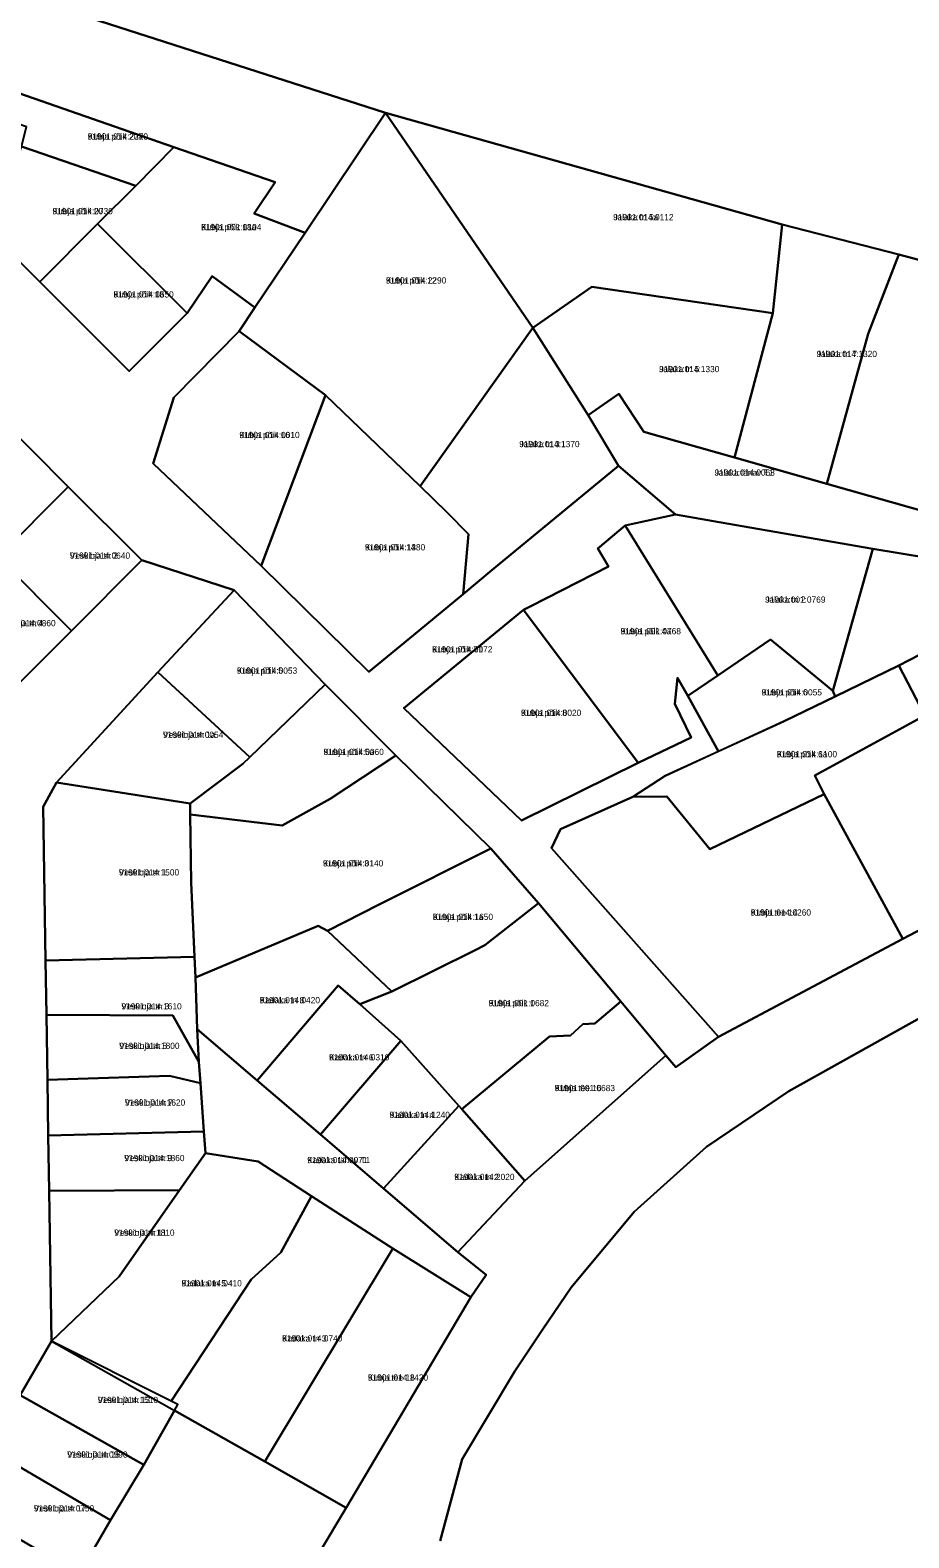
# Model space of a CAD drawing. Extents: x 675810 to 681273, y 6411190 to 6417565.
# Drawn here: x 678392.3 to 678603.7, y 6413180.1 to 6413542.7 of the extents above; entities that cross this region are included whole.
import ezdxf

# ---------------------------------------------------------------- set-up
doc = ezdxf.new("R2010")
doc.units = 0
for name, color, linetype in [('L_AADRESS', 7, 'Continuous'), ('PIIR', 7, 'Continuous'), ('TUNNUS', 7, 'Continuous')]:
    doc.layers.add(name, color=color, linetype=linetype)

msp = doc.modelspace()

# ---------------------------------------------------------------- linework, layer by layer
at = {"layer": 'PIIR'}
for points in [[(678295.76, 6413554.98), (678293.96, 6413581.95), (678477.82, 6413522.85), (678458.5, 6413494.01), (678446.21, 6413498.66), (678451.25, 6413506.22), (678426.9, 6413514.62), (678389.61, 6413527.56), (678354.34, 6413542.49), (678352.55, 6413514.04), (678351.25, 6413513.9), (678354.14, 6413492.79), (678351.28, 6413483.5), (678325.9, 6413492.81), (678311.61, 6413482.73), (678306.63, 6413471.48), (678306.92, 6413457.06), (678308.78, 6413450.62), (678302.83, 6413437.81), (678298.35, 6413440.16), (678297.78, 6413528.19)], [(678426.9, 6413514.62), (678417.74, 6413505.28), (678390.19, 6413514.73), (678391.4, 6413519.53), (678387.5, 6413520.85), (678389.61, 6413527.56)], [(678513.24, 6413471.19), (678486.13, 6413433.07), (678463.36, 6413454.98), (678442.64, 6413470.33), (678446.41, 6413476.03), (678458.5, 6413494.01), (678477.82, 6413522.85)], [(678477.82, 6413522.85), (678573.26, 6413496.02), (678571.03, 6413474.68), (678527.43, 6413480.98), (678513.24, 6413471.19)], [(678386.16, 6413490.69), (678382.36, 6413492.05), (678390.19, 6413514.73), (678417.74, 6413505.28), (678408.5, 6413496.18), (678394.65, 6413482.21)], [(678417.74, 6413505.28), (678426.9, 6413514.62), (678451.25, 6413506.22), (678446.21, 6413498.66), (678458.5, 6413494.01), (678446.41, 6413476.03), (678436.09, 6413483.57), (678430.1, 6413474.66), (678408.5, 6413496.18)], [(678394.65, 6413482.21), (678408.5, 6413496.18), (678430.1, 6413474.66), (678416.16, 6413460.72)], [(678571.03, 6413474.68), (678573.26, 6413496.02), (678601.35, 6413488.77), (678593.96, 6413469.73), (678584.01, 6413433.67), (678561.79, 6413440)], [(678593.96, 6413469.73), (678601.35, 6413488.77), (678622.33, 6413483.15), (678627.53, 6413450.29), (678630.17, 6413428.46), (678609.77, 6413426.33), (678584.01, 6413433.67)], [(678513.24, 6413471.19), (678527.43, 6413480.98), (678571.03, 6413474.68), (678561.79, 6413440), (678540, 6413446.17), (678533.98, 6413455.3), (678526.6, 6413450.17)], [(678421.94, 6413438.53), (678426.87, 6413454.38), (678442.64, 6413470.33), (678463.36, 6413454.98), (678447.92, 6413413.95)], [(678497.82, 6413421.55), (678492.57, 6413426.8), (678486.13, 6413433.07), (678513.24, 6413471.19), (678526.6, 6413450.17), (678533.88, 6413437.98), (678503.42, 6413412.83), (678496.47, 6413407.1)], [(678447.92, 6413413.95), (678463.36, 6413454.98), (678486.13, 6413433.07), (678492.57, 6413426.8), (678497.82, 6413421.55), (678496.47, 6413407.1), (678485.89, 6413398.35), (678473.84, 6413388.45)], [(678526.6, 6413450.17), (678533.98, 6413455.3), (678540, 6413446.17), (678561.79, 6413440), (678584.01, 6413433.67), (678609.77, 6413426.33), (678630.17, 6413428.46), (678631.49, 6413420.57), (678608.2, 6413415.87), (678595.07, 6413418.02), (678559.91, 6413424.12), (678547.61, 6413426.26), (678533.88, 6413437.98)], [(678384.53, 6413415.96), (678354.7, 6413416.01), (678348.57, 6413416.03), (678317.48, 6413417.46), (678306.94, 6413412.98), (678309.26, 6413408.27), (678292.44, 6413401.19), (678293.98, 6413418.76), (678317.17, 6413427.45), (678331, 6413421.85), (678345.66, 6413423.1), (678356.55, 6413422.98), (678383.8, 6413450.61), (678401.49, 6413432.94)], [(678402.22, 6413398.29), (678384.53, 6413415.96), (678401.49, 6413432.94), (678419.18, 6413415.28)], [(678557.76, 6413387.54), (678535.45, 6413423.61), (678547.61, 6413426.26), (678559.91, 6413424.12), (678595.07, 6413418.02), (678585.46, 6413383.81), (678570.48, 6413396.2)], [(678535.45, 6413423.61), (678557.76, 6413387.54), (678550.59, 6413382.64), (678548.06, 6413386.98), (678547.45, 6413380.71), (678551.39, 6413372.61), (678538.62, 6413366.54), (678511.05, 6413403.34), (678512.66, 6413404.15), (678520.31, 6413408.07), (678531.49, 6413413.74), (678528.93, 6413418.05)], [(678585.46, 6413383.81), (678595.07, 6413418.02), (678608.2, 6413415.87), (678631.49, 6413420.57), (678633.57, 6413405.93), (678618.75, 6413398.88), (678601.3, 6413389.95), (678586.02, 6413382.5)], [(678348.37, 6413407.11), (678319.56, 6413412.48), (678309.26, 6413408.27), (678306.94, 6413412.98), (678317.48, 6413417.46), (678348.57, 6413416.03), (678354.7, 6413416.01), (678384.53, 6413415.96), (678402.22, 6413398.29), (678385.26, 6413381.3), (678358.97, 6413406.95)], [(678441.41, 6413408.05), (678463.27, 6413385.35), (678445.14, 6413367.88), (678422.99, 6413388.32)], [(678627.38, 6413341.21), (678613.08, 6413367.48), (678608.23, 6413376.32), (678607.62, 6413377.91), (678601.3, 6413389.95), (678618.75, 6413398.88), (678633.57, 6413405.93), (678637.71, 6413407.92), (678650.35, 6413387.95), (678630.94, 6413377.1), (678645.38, 6413350.73)], [(678538.62, 6413366.54), (678510.55, 6413352.67), (678482.22, 6413379.65), (678511.05, 6413403.34)], [(678557.76, 6413387.54), (678570.48, 6413396.2), (678585.46, 6413383.81), (678586.02, 6413382.5), (678573.76, 6413376.53), (678557.92, 6413369.29), (678550.59, 6413382.64)], [(678545.52, 6413358.41), (678537.34, 6413358.32), (678545.11, 6413363.44), (678557.92, 6413369.3), (678573.76, 6413376.53), (678586.02, 6413382.5), (678601.3, 6413389.95), (678607.62, 6413377.91), (678581.15, 6413363.52), (678583.38, 6413358.97), (678555.83, 6413345.79)], [(678422.99, 6413388.32), (678445.14, 6413367.88), (678443.51, 6413366.32), (678430.85, 6413356.78), (678398.62, 6413361.82)], [(678463.27, 6413385.35), (678480.26, 6413368.28), (678464.49, 6413357.91), (678452.98, 6413351.45), (678430.78, 6413354.14), (678430.85, 6413356.78), (678443.51, 6413366.32), (678445.14, 6413367.88)], [(678583.38, 6413358.97), (678581.15, 6413363.52), (678607.62, 6413377.91), (678608.23, 6413376.32), (678613.08, 6413367.48), (678627.38, 6413341.21), (678628.99, 6413338.24), (678602.33, 6413324.19)], [(678432.09, 6413314.94), (678431.86, 6413319.86), (678431.02, 6413337.78), (678430.78, 6413354.14), (678452.98, 6413351.45), (678464.49, 6413357.91), (678480.26, 6413368.28), (678503.19, 6413345.91), (678476.32, 6413332.49), (678463.84, 6413326.15), (678461.61, 6413327.29)], [(678431.86, 6413319.86), (678396.01, 6413318.99), (678395.44, 6413355.92), (678398.62, 6413361.82), (678430.85, 6413356.78), (678430.78, 6413354.14), (678431.02, 6413337.78)], [(678602.33, 6413324.19), (678557.93, 6413300.6), (678517.78, 6413346), (678519.93, 6413350.6), (678537.34, 6413358.32), (678545.52, 6413358.41), (678555.83, 6413345.79), (678583.38, 6413358.97)], [(678463.84, 6413326.15), (678476.32, 6413332.49), (678503.19, 6413345.91), (678514.61, 6413332.78), (678512.39, 6413331.01), (678501.73, 6413322.67), (678499.37, 6413321.5), (678479.34, 6413311.54)], [(678512.39, 6413331.01), (678514.61, 6413332.78), (678534.4, 6413309.14), (678528.18, 6413303.83), (678525.32, 6413303.69), (678522.35, 6413300.94), (678517.28, 6413300.68), (678496.18, 6413283.21), (678495.48, 6413284), (678481.52, 6413299.63), (678471.66, 6413308.5), (678479.34, 6413311.54), (678499.37, 6413321.5), (678501.73, 6413322.67)], [(678466.42, 6413312.94), (678446.94, 6413290.13), (678432.5, 6413302.46), (678432.09, 6413314.94), (678461.61, 6413327.29), (678463.84, 6413326.15), (678479.34, 6413311.54), (678471.66, 6413308.5)], [(678426.61, 6413305.8), (678396.21, 6413305.95), (678396.01, 6413318.99), (678431.86, 6413319.86), (678432.09, 6413314.94), (678432.5, 6413302.46), (678432.92, 6413294.58)], [(678446.94, 6413290.13), (678466.42, 6413312.94), (678471.66, 6413308.5), (678481.52, 6413299.63), (678462.15, 6413277.13)], [(678528.18, 6413303.83), (678534.4, 6413309.14), (678545.3, 6413296.17), (678511.35, 6413266), (678496.18, 6413283.21), (678517.28, 6413300.68), (678522.35, 6413300.94), (678525.32, 6413303.69)], [(678425.81, 6413291.23), (678396.46, 6413290.3), (678396.21, 6413305.95), (678426.61, 6413305.8), (678432.92, 6413294.58), (678433.29, 6413289.47)], [(678432.5, 6413302.46), (678446.94, 6413290.13), (678462.15, 6413277.13), (678477.36, 6413264.14), (678495.22, 6413248.88), (678502.03, 6413243.37), (678498.35, 6413238.03), (678479.59, 6413249.75), (678460.03, 6413262.33), (678447.16, 6413270.61), (678434.5, 6413272.68), (678434.13, 6413277.9), (678433.29, 6413289.47), (678432.92, 6413294.58)], [(678462.15, 6413277.13), (678481.52, 6413299.63), (678495.48, 6413284), (678477.36, 6413264.14)], [(678434.13, 6413277.9), (678396.67, 6413276.93), (678396.46, 6413290.3), (678425.81, 6413291.23), (678433.29, 6413289.47)], [(678495.22, 6413248.88), (678477.36, 6413264.14), (678495.48, 6413284), (678496.18, 6413283.21), (678511.35, 6413266)], [(678428.22, 6413263.74), (678396.88, 6413263.56), (678396.67, 6413276.93), (678434.13, 6413277.9), (678434.5, 6413272.68)], [(678452.59, 6413248.73), (678445.5, 6413242.24), (678426.27, 6413212.98), (678397.45, 6413227.43), (678413.7, 6413243.03), (678428.22, 6413263.74), (678434.5, 6413272.68), (678447.16, 6413270.61), (678460.03, 6413262.33)], [(678413.7, 6413243.03), (678397.45, 6413227.43), (678396.88, 6413263.56), (678428.22, 6413263.74)], [(678427.06, 6413210.73), (678427.88, 6413212.17), (678426.27, 6413212.98), (678445.5, 6413242.24), (678452.59, 6413248.73), (678460.03, 6413262.33), (678479.59, 6413249.75), (678448.79, 6413198.47)], [(678479.59, 6413249.75), (678498.35, 6413238.03), (678468.34, 6413187.35), (678448.79, 6413198.47)], [(678397.45, 6413227.43), (678427.06, 6413210.73), (678419.68, 6413197.67), (678389.92, 6413214.47)], [(678389.92, 6413214.47), (678419.68, 6413197.67), (678411.67, 6413184.37), (678382.31, 6413201.53)], [(678435.46, 6413132.45), (678399.43, 6413154.72), (678395.78, 6413156.89), (678366.24, 6413174.06), (678374.74, 6413188.57), (678404.1, 6413171.42), (678411.67, 6413184.37), (678419.68, 6413197.67), (678427.06, 6413210.73), (678448.79, 6413198.47), (678468.34, 6413187.35)], [(678382.31, 6413201.53), (678411.67, 6413184.37), (678404.1, 6413171.42), (678374.74, 6413188.57)]]:
    msp.add_lwpolyline(points, close=True, dxfattribs=at)
for points in [[(678858.38, 6413443.59), (678779.84, 6413441.57), (678734.44, 6413455.67), (678700.16, 6413460.78), (678680.14, 6413465.61), (678622.33, 6413483.15), (678601.35, 6413488.77), (678573.26, 6413496.02), (678477.82, 6413522.85), (678293.96, 6413581.95)], [(678386.16, 6413490.69), (678394.65, 6413482.21), (678416.16, 6413460.72), (678430.1, 6413474.66), (678436.09, 6413483.57), (678446.41, 6413476.03), (678442.64, 6413470.33), (678426.87, 6413454.38), (678421.94, 6413438.53), (678447.92, 6413413.95), (678473.84, 6413388.45), (678485.89, 6413398.35), (678496.47, 6413407.1), (678503.42, 6413412.83), (678533.88, 6413437.98), (678547.61, 6413426.26), (678535.45, 6413423.61), (678528.93, 6413418.05), (678531.49, 6413413.74), (678520.31, 6413408.07), (678512.66, 6413404.15), (678511.05, 6413403.34), (678482.22, 6413379.65), (678510.55, 6413352.67), (678538.62, 6413366.54), (678551.39, 6413372.61), (678547.45, 6413380.71), (678548.06, 6413386.98), (678550.59, 6413382.64), (678557.92, 6413369.29), (678545.11, 6413363.44), (678537.34, 6413358.32), (678519.93, 6413350.6), (678517.78, 6413346), (678557.93, 6413300.6), (678547.71, 6413293.36), (678545.3, 6413296.17), (678534.4, 6413309.14), (678514.61, 6413332.78), (678503.19, 6413345.91), (678480.26, 6413368.28), (678463.27, 6413385.35), (678441.41, 6413408.05), (678419.18, 6413415.28), (678401.49, 6413432.94), (678383.8, 6413450.61)], [(678435.46, 6413132.45), (678468.34, 6413187.35), (678498.35, 6413238.03), (678502.03, 6413243.37), (678495.22, 6413248.88), (678511.35, 6413266), (678545.3, 6413296.17), (678547.71, 6413293.36), (678557.93, 6413300.6), (678602.33, 6413324.19), (678628.99, 6413338.24), (678627.38, 6413341.21), (678645.38, 6413350.73), (678665.04, 6413361.36), (678666.81, 6413358.15), (678710.5, 6413387.05), (678745.28, 6413416.24), (678779.84, 6413441.57), (678858.38, 6413443.59)], [(678385.26, 6413381.3), (678402.22, 6413398.29), (678419.18, 6413415.28), (678441.41, 6413408.05), (678422.99, 6413388.32), (678398.62, 6413361.82), (678395.44, 6413355.92), (678396.01, 6413318.99), (678396.21, 6413305.95), (678396.46, 6413290.3), (678396.67, 6413276.93), (678396.88, 6413263.56), (678397.45, 6413227.43), (678389.92, 6413214.47)], [(678837.49, 6413412.16), (678813.86, 6413408.99), (678791.56, 6413403.6), (678770.01, 6413395.44), (678749.7, 6413384.68), (678709.22, 6413356.39), (678663.86, 6413332.17), (678641.85, 6413320.32), (678618.17, 6413311.55), (678607.18, 6413305.63), (678574.88, 6413287.6), (678555.09, 6413274.2), (678537.66, 6413258.57), (678522.47, 6413240.32), (678515.7, 6413230.29), (678508.92, 6413220.26), (678502.59, 6413209.66), (678496.26, 6413199.06), (678490.99, 6413179.42)], [(678490.99, 6413179.42), (678496.26, 6413199.06), (678502.59, 6413209.66), (678508.92, 6413220.26), (678515.7, 6413230.29), (678522.47, 6413240.32), (678537.66, 6413258.57), (678555.09, 6413274.2), (678574.88, 6413287.6), (678607.18, 6413305.63), (678618.17, 6413311.55), (678641.85, 6413320.32), (678663.86, 6413332.17), (678709.22, 6413356.39), (678749.7, 6413384.68), (678770.01, 6413395.44), (678791.56, 6413403.6), (678802.33, 6413329.46), (678796.69, 6413254.97), (678802.47, 6413186.73), (678806.01, 6413088.59)]]:
    msp.add_lwpolyline(points, dxfattribs=at)

# ---------------------------------------------------------------- texts
at = {"layer": 'L_AADRESS'}
for s, p in [('Kubja põik 20a', (678406.16, 6413516.42)), ('Kubja põik 20', (678397.7, 6413498.47)), ('Jalaka tn 5a', (678532.62, 6413497.02)), ('Kubja põik 18a', (678433.44, 6413494.64)), ('Kubja põik 12', (678477.94, 6413481.81)), ('Kubja põik 18', (678412.35, 6413478.45)), ('Jalaka tn 7', (678581.57, 6413464.12)), ('Jalaka tn 5', (678543.65, 6413460.49)), ('Kubja põik 16', (678442.65, 6413444.63)), ('Jalaka tn 3', (678510.01, 6413442.45)), ('Jalaka tänav T1', (678556.99, 6413435.59)), ('Kubja põik 14', (678472.87, 6413417.62)), ('Veskioja tn 2', (678401.86, 6413415.62)), ('Jalaka tn 2', (678569.18, 6413405.04)), ('Veskioja tn 4', (678383.93, 6413399.38)), ('Kubja põik 4a', (678534.4, 6413397.44)), ('Kubja põik T1', (678489.03, 6413393.08)), ('Kubja põik 5', (678442.06, 6413387.96)), ('Kubja põik 6', (678568.33, 6413382.74)), ('Kubja põik 8', (678510.42, 6413377.81)), ('Veskioja tn 1a', (678424.28, 6413372.55)), ('Kubja põik 5a', (678462.91, 6413368.4)), ('Kubja põik 6a', (678571.97, 6413367.87)), ('Kubja põik 3', (678462.77, 6413341.61)), ('Veskioja tn 1', (678413.65, 6413339.44)), ('Kubja tee 14', (678565.7, 6413329.79)), ('Kubja põik 1a', (678489.19, 6413328.73)), ('Kadaka tn 8', (678447.55, 6413308.71)), ('Kubja põik 1', (678502.64, 6413308)), ('Veskioja tn 3', (678414.27, 6413307.22)), ('Veskioja tn 5', (678413.75, 6413297.71)), ('Kadaka tn 6', (678464.23, 6413294.96)), ('Kubja tee 16', (678518.53, 6413287.57)), ('Veskioja tn 7', (678415.12, 6413284.08)), ('Kadaka tn 4', (678478.81, 6413281.11)), ('Veskioja tn 9', (678414.95, 6413270.73)), ('Kadaka tänav T1', (678458.97, 6413270.25)), ('Kadaka tn 2', (678494.36, 6413266.19)), ('Veskioja tn 11', (678412.55, 6413252.79)), ('Kadaka tn 5', (678428.74, 6413240.61)), ('Kadaka tn 3', (678452.93, 6413227.36)), ('Kubja tee 18', (678473.57, 6413217.95)), ('Veskioja tn 13', (678408.58, 6413212.55)), ('Veskioja tn 15', (678401.25, 6413199.42)), ('Veskioja tn 17', (678393.2, 6413186.48))]:
    msp.add_text(s, height=1.5, dxfattribs=at).set_placement(p)
at = {"layer": 'TUNNUS'}
for s, p in [('91901:014:2270', (678406.16, 6413516.42)), ('91901:014:0730', (678397.7, 6413498.47)), ('91901:014:0112', (678532.62, 6413497.02)), ('91901:001:0104', (678433.44, 6413494.64)), ('91901:014:2290', (678477.94, 6413481.81)), ('91901:014:0650', (678412.35, 6413478.45)), ('91901:014:1320', (678581.57, 6413464.12)), ('91901:014:1330', (678543.65, 6413460.49)), ('91901:014:0010', (678442.65, 6413444.63)), ('91901:014:1370', (678510.01, 6413442.45)), ('91901:014:0068', (678556.99, 6413435.59)), ('91901:014:1380', (678472.87, 6413417.62)), ('91901:014:0640', (678401.86, 6413415.62)), ('91901:001:0769', (678569.18, 6413405.04)), ('91901:014:0860', (678383.93, 6413399.38)), ('91901:001:0768', (678534.4, 6413397.44)), ('91901:014:0072', (678489.03, 6413393.08)), ('91901:014:0053', (678442.06, 6413387.96)), ('91901:014:0055', (678568.33, 6413382.74)), ('91901:014:0020', (678510.42, 6413377.81)), ('91901:014:0054', (678424.28, 6413372.55)), ('91901:014:0060', (678462.91, 6413368.4)), ('91901:014:1100', (678571.97, 6413367.87)), ('91901:014:0140', (678462.77, 6413341.61)), ('91901:014:1500', (678413.65, 6413339.44)), ('91901:014:0260', (678565.7, 6413329.79)), ('91901:014:1650', (678489.19, 6413328.73)), ('91901:014:0420', (678447.55, 6413308.71)), ('91901:001:0682', (678502.64, 6413308)), ('91901:014:1610', (678414.27, 6413307.22)), ('91901:014:1800', (678413.75, 6413297.71)), ('91901:014:0310', (678464.23, 6413294.96)), ('91901:001:0683', (678518.53, 6413287.57)), ('91901:014:1620', (678415.12, 6413284.08)), ('91901:014:1240', (678478.81, 6413281.11)), ('91901:014:1860', (678414.95, 6413270.73)), ('91901:014:0071', (678458.97, 6413270.25)), ('91901:014:2020', (678494.36, 6413266.19)), ('91901:014:1810', (678412.55, 6413252.79)), ('91901:014:0410', (678428.74, 6413240.61)), ('91901:014:0740', (678452.93, 6413227.36)), ('91901:014:1420', (678473.57, 6413217.95)), ('91901:014:1510', (678408.58, 6413212.55)), ('91901:014:0990', (678401.25, 6413199.42)), ('91901:014:0750', (678393.2, 6413186.48))]:
    msp.add_text(s, height=1.5, dxfattribs=at).set_placement(p)

doc.saveas('drawing.dxf')
